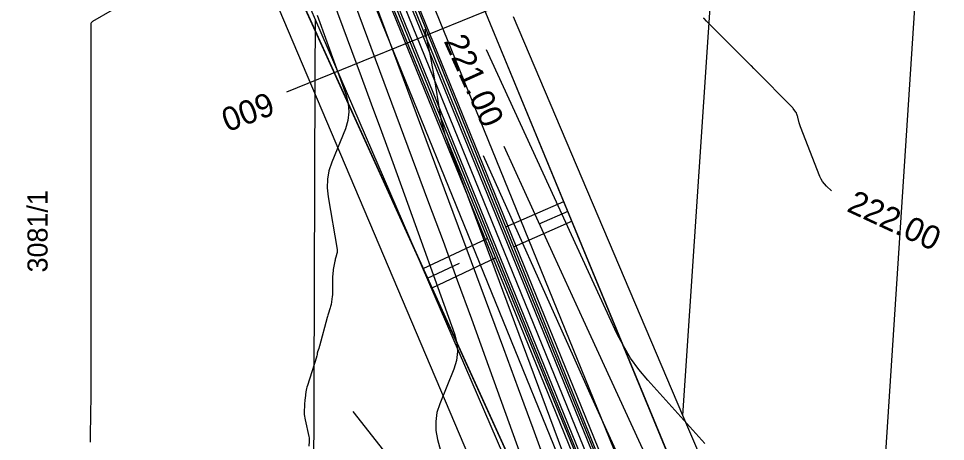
# Model space of a CAD drawing. Extents: x -534410 to -534262, y -1190162 to -1189584.
# Drawn here: x -534354.45 to -534315.26, y -1189992.54 to -1189974.68 of the extents above; entities that cross this region are included whole.
import ezdxf

# ---------------------------------------------------------------- set-up
doc = ezdxf.new("R2010")
doc.units = 0
for name, color, linetype in [('30', 7, 'Continuous'), ('31', 7, 'Continuous'), ('40', 7, 'Continuous'), ('_linie', 7, 'Continuous'), ('_N_osa', 7, 'Continuous'), ('_N_tenká', 7, 'Continuous'), ('_N_tenká_velmi', 7, 'Continuous'), ('_N_text', 7, 'Continuous'), ('_přístup', 7, 'Continuous'), ('_tenka', 7, 'Continuous'), ('_velmi_tenka', 7, 'Continuous'), ('Default', 7, 'Continuous'), ('Hranice parcel', 7, 'Continuous'), ('Parcelní čísla', 7, 'Continuous'), ('Vrstva 12', 7, 'Continuous')]:
    doc.layers.add(name, color=color, linetype=linetype)

msp = doc.modelspace()

# ---------------------------------------------------------------- linework, layer by layer
at = {"layer": '30'}
for points in [[(-534332.074, -1189993.689), (-534332.691, -1189991.999), (-534333.312, -1189990.311), (-534333.937, -1189988.624), (-534345.745, -1189956.862)], [(-534346.256, -1189960.213), (-534339.969, -1189977.123), (-534339.54, -1189978.283), (-534339.113, -1189979.443), (-534338.689, -1189980.605), (-534338.267, -1189981.768), (-534336.016, -1189988), (-534335.917, -1189988.373), (-534335.889, -1189988.744), (-534335.932, -1189989.113), (-534336.046, -1189989.482), (-534336.644, -1189990.952), (-534336.762, -1189991.321), (-534336.816, -1189991.694), (-534336.807, -1189992.071), (-534336.734, -1189992.452), (-534335.832, -1189995.749)], [(-534350.497, -1189974.321), (-534351.326, -1189974.802), (-534351.359, -1189974.826), (-534351.382, -1189974.855), (-534351.396, -1189974.89), (-534351.4, -1189974.93), (-534351.401, -1189975.144), (-534351.401, -1189975.273), (-534351.401, -1189976.416), (-534351.401, -1189976.545), (-534351.4, -1189976.759), (-534351.4, -1189976.845), (-534351.4, -1189976.93), (-534351.401, -1189977.144), (-534351.401, -1189977.273), (-534351.401, -1189978.416), (-534351.401, -1189978.545), (-534351.4, -1189978.759), (-534351.4, -1189978.845), (-534351.4, -1189978.93), (-534351.401, -1189979.144), (-534351.401, -1189979.273), (-534351.401, -1189980.416), (-534351.401, -1189980.545), (-534351.4, -1189980.759), (-534351.4, -1189980.845), (-534351.4, -1189980.93), (-534351.401, -1189981.144), (-534351.401, -1189981.273), (-534351.401, -1189982.416), (-534351.401, -1189982.545), (-534351.4, -1189982.759), (-534351.4, -1189982.845), (-534351.4, -1189982.93), (-534351.401, -1189983.144), (-534351.401, -1189983.273), (-534351.401, -1189984.416), (-534351.401, -1189984.545), (-534351.4, -1189984.759), (-534351.4, -1189984.845), (-534351.4, -1189984.93), (-534351.401, -1189985.144), (-534351.401, -1189985.273), (-534351.401, -1189986.416), (-534351.401, -1189986.545), (-534351.4, -1189986.759), (-534351.4, -1189986.845), (-534351.4, -1189986.93), (-534351.401, -1189987.144), (-534351.401, -1189987.273), (-534351.401, -1189988.416), (-534351.401, -1189988.545), (-534351.4, -1189988.759), (-534351.4, -1189988.845), (-534351.4, -1189988.93), (-534351.401, -1189989.144), (-534351.401, -1189989.273), (-534351.401, -1189990.416), (-534351.401, -1189990.545), (-534351.4, -1189990.762), (-534351.401, -1189990.803), (-534351.401, -1189990.844), (-534351.402, -1189990.886), (-534351.404, -1189990.927), (-534351.411, -1189991.091), (-534351.412, -1189991.132), (-534351.413, -1189991.174), (-534351.414, -1189991.215), (-534351.415, -1189991.256), (-534351.424, -1189992.446), (-534351.424, -1189992.486), (-534351.425, -1189992.526), (-534351.426, -1189992.566)], [(-534320.077, -1189981.949), (-534320.294, -1189981.749), (-534320.38, -1189981.66), (-534320.454, -1189981.563), (-534320.517, -1189981.458), (-534320.569, -1189981.346), (-534321.392, -1189979.243), (-534321.406, -1189979.204), (-534321.419, -1189979.165), (-534321.431, -1189979.125), (-534321.442, -1189979.085), (-534321.491, -1189978.891), (-534321.497, -1189978.868), (-534321.504, -1189978.845), (-534321.51, -1189978.822), (-534321.517, -1189978.799), (-534321.546, -1189978.707), (-534321.554, -1189978.685), (-534321.564, -1189978.663), (-534321.575, -1189978.643), (-534321.588, -1189978.623), (-534321.697, -1189978.473), (-534321.721, -1189978.442), (-534321.745, -1189978.412), (-534321.771, -1189978.383), (-534321.798, -1189978.355), (-534323.254, -1189976.899), (-534323.281, -1189976.872), (-534323.308, -1189976.844), (-534323.335, -1189976.817), (-534323.362, -1189976.789), (-534323.469, -1189976.679), (-534323.496, -1189976.652), (-534323.523, -1189976.624), (-534323.55, -1189976.597), (-534323.578, -1189976.571), (-534323.688, -1189976.463), (-534323.715, -1189976.436), (-534323.743, -1189976.41), (-534323.77, -1189976.382), (-534323.797, -1189976.355), (-534325.254, -1189974.899), (-534325.281, -1189974.872), (-534325.308, -1189974.844), (-534325.335, -1189974.817), (-534325.362, -1189974.789), (-534325.469, -1189974.679), (-534325.496, -1189974.652)], [(-534333.934, -1189980.069), (-534333.065, -1189981.984), (-534331.827, -1189984.695), (-534330.583, -1189987.403), (-534324.037, -1190001.603)]]:
    msp.add_lwpolyline(points, dxfattribs=at)
at = {"layer": '31'}
for points in [[(-534346.466, -1189957.285), (-534337.113, -1189982.443), (-534336.506, -1189984.081), (-534335.903, -1189985.722), (-534335.304, -1189987.363), (-534334.708, -1189989.006), (-534331.253, -1189998.572)], [(-534341.826, -1189974.529), (-534340.607, -1189977.906), (-534340.511, -1189978.264), (-534340.484, -1189978.621), (-534340.525, -1189978.977), (-534340.635, -1189979.331), (-534341.211, -1189980.746), (-534341.328, -1189981.103), (-534341.394, -1189981.465), (-534341.407, -1189981.832), (-534341.368, -1189982.206), (-534340.983, -1189984.424), (-534340.978, -1189984.466), (-534340.977, -1189984.509), (-534340.982, -1189984.551), (-534340.991, -1189984.593), (-534341.037, -1189984.761), (-534341.048, -1189984.803), (-534341.059, -1189984.845), (-534341.068, -1189984.887), (-534341.077, -1189984.93), (-534341.145, -1189985.272), (-534341.157, -1189985.343), (-534341.166, -1189985.415), (-534341.171, -1189985.487), (-534341.173, -1189985.56), (-534341.173, -1189986.131), (-534341.174, -1189986.203), (-534341.178, -1189986.274), (-534341.185, -1189986.346), (-534341.193, -1189986.417), (-534341.241, -1189986.749), (-534341.248, -1189986.796), (-534341.258, -1189986.843), (-534341.271, -1189986.89), (-534341.285, -1189986.936), (-534341.346, -1189987.119), (-534341.361, -1189987.165), (-534341.376, -1189987.211), (-534341.389, -1189987.257), (-534341.402, -1189987.304), (-534341.729, -1189988.516), (-534341.736, -1189988.542), (-534341.744, -1189988.568), (-534341.753, -1189988.593), (-534341.762, -1189988.619), (-534341.811, -1189988.753), (-534341.814, -1189988.762), (-534341.816, -1189988.771), (-534341.818, -1189988.78), (-534341.82, -1189988.789), (-534341.826, -1189988.826), (-534341.829, -1189988.844), (-534341.832, -1189988.863), (-534341.844, -1189988.924), (-534341.846, -1189988.937), (-534341.85, -1189988.95), (-534341.853, -1189988.963), (-534341.857, -1189988.976), (-534342.241, -1189990.175), (-534342.261, -1189990.24), (-534342.277, -1189990.306), (-534342.291, -1189990.373), (-534342.302, -1189990.44), (-534342.339, -1189990.71), (-534342.347, -1189990.777), (-534342.354, -1189990.845), (-534342.358, -1189990.913), (-534342.361, -1189990.981), (-534342.371, -1189991.319), (-534342.371, -1189991.398), (-534342.365, -1189991.476), (-534342.355, -1189991.554), (-534342.34, -1189991.631), (-534342.181, -1189992.329), (-534342.171, -1189992.38), (-534342.165, -1189992.431), (-534342.162, -1189992.482), (-534342.163, -1189992.534), (-534342.173, -1189992.741)], [(-534330.139, -1189996.477), (-534336.286, -1189979.943), (-534336.394, -1189979.631), (-534336.486, -1189979.315), (-534336.563, -1189978.994), (-534336.624, -1189978.67), (-534336.869, -1189977.175), (-534336.908, -1189976.943), (-534336.95, -1189976.711), (-534336.994, -1189976.479), (-534337.042, -1189976.248), (-534337.235, -1189975.325), (-534337.265, -1189975.15), (-534337.262, -1189975.118)], [(-534325.433, -1189992.626), (-534327.845, -1189989.955), (-534328.228, -1189989.497), (-534328.573, -1189989.014), (-534328.881, -1189988.507), (-534329.151, -1189987.974), (-534334.672, -1189975.998)], [(-534334.815, -1189980.466), (-534330.995, -1189988.966), (-534330.298, -1189990.512), (-534329.597, -1189992.056), (-534328.893, -1189993.598), (-534328.185, -1189995.139), (-534325.187, -1190001.643), (-534324.603, -1190003.024), (-534324.113, -1190004.435), (-534323.717, -1190005.875), (-534323.414, -1190007.344), (-534322.095, -1190014.986), (-534321.984, -1190015.614), (-534321.868, -1190016.242), (-534321.747, -1190016.868), (-534321.621, -1190017.494), (-534321.51, -1190018.033)]]:
    msp.add_lwpolyline(points, dxfattribs=at)
at = {"layer": '_linie'}
for points in [[(-534351.8, -1189951.99), (-534346.88, -1189964.25), (-534328.11, -1190005.55), (-534325.796, -1190021.686), (-534325.86, -1190050.97), (-534326.22, -1190078.56), (-534326.79, -1190120.4), (-534329.12, -1190134.93), (-534323.49, -1190133.89), (-534321.38, -1190121.46), (-534319.59, -1190053.22), (-534320.45, -1190021.195), (-534322.75, -1190003.33), (-534340.65, -1189960.04), (-534344.52, -1189948.89)], [(-534347.45, -1189950.137), (-534345.54, -1189954.54), (-534325.02, -1190005.35), (-534322.054, -1190021.393), (-534321.72, -1190051.56), (-534322.31, -1190078.15), (-534323.81, -1190120.37), (-534326.521, -1190134.45)], [(-534328.194, -1190134.759), (-534324.85, -1190120.45), (-534324.6, -1190078.17), (-534323.54, -1190051.92), (-534323.273, -1190021.516), (-534325.81, -1190005.43), (-534346.66, -1189954.59), (-534348.342, -1189950.518)]]:
    msp.add_lwpolyline(points, dxfattribs=at)
at = {"layer": '_N_osa'}
msp.add_lwpolyline([(-534327.357, -1190134.604), (-534324.33, -1190120.41), (-534323.455, -1190078.16), (-534322.63, -1190051.74), (-534322.663, -1190021.455), (-534325.415, -1190005.39), (-534346.1, -1189954.565), (-534347.892, -1189950.326)], dxfattribs=at)
at = {"layer": '_N_tenká'}
for points in [[(-534326.133, -1190134.378), (-534323.183, -1190120.543), (-534322.305, -1190078.19), (-534321.48, -1190051.757), (-534321.513, -1190021.356), (-534324.303, -1190005.072), (-534345.038, -1189954.124), (-534346.832, -1189949.878)], [(-534327.623, -1190134.654), (-534324.579, -1190120.381), (-534323.705, -1190078.154), (-534322.88, -1190051.736), (-534322.913, -1190021.476), (-534325.657, -1190005.459), (-534346.331, -1189954.661), (-534348.122, -1189950.423)], [(-534327.091, -1190134.555), (-534324.081, -1190120.439), (-534323.205, -1190078.166), (-534322.38, -1190051.744), (-534322.413, -1190021.433), (-534325.173, -1190005.321), (-534345.869, -1189954.469), (-534347.661, -1189950.228)], [(-534328.581, -1190134.83), (-534325.477, -1190120.277), (-534324.605, -1190078.13), (-534323.78, -1190051.723), (-534323.813, -1190021.553), (-534326.527, -1190005.708), (-534347.162, -1189955.006), (-534348.951, -1189950.773)]]:
    msp.add_lwpolyline(points, dxfattribs=at)
at = {"layer": '_N_tenká_velmi'}
for points in [[(-534326.772, -1190134.496), (-534323.781, -1190120.474), (-534322.905, -1190078.174), (-534322.08, -1190051.748), (-534322.113, -1190021.407), (-534324.883, -1190005.238), (-534345.592, -1189954.354), (-534347.385, -1189950.112)], [(-534327.943, -1190134.713), (-534324.879, -1190120.346), (-534324.005, -1190078.146), (-534323.18, -1190051.732), (-534323.213, -1190021.502), (-534325.947, -1190005.542), (-534346.608, -1189954.776), (-534348.398, -1189950.54)], [(-534327.73, -1190134.673), (-534324.679, -1190120.37), (-534323.805, -1190078.151), (-534322.98, -1190051.735), (-534323.013, -1190021.485), (-534325.754, -1190005.487), (-534346.423, -1189954.699), (-534348.214, -1189950.462)], [(-534326.985, -1190134.536), (-534323.981, -1190120.45), (-534323.105, -1190078.169), (-534322.28, -1190051.745), (-534322.313, -1190021.425), (-534325.076, -1190005.293), (-534345.777, -1189954.431), (-534347.569, -1189950.189)]]:
    msp.add_lwpolyline(points, dxfattribs=at)
at = {"layer": '_N_text'}
msp.add_lwpolyline([(-534332.014, -1189973.259), (-534343.129, -1189977.783)], dxfattribs=at)
at = {"layer": '_přístup'}
msp.add_lwpolyline([(-534330.552, -1190135.191), (-534328.648, -1190119.819), (-534326.845, -1190024.247), (-534332.805, -1189999.297), (-534354.454, -1189948.317)], dxfattribs=at)
at = {"layer": '_tenka'}
for points in [[(-534351.8, -1189951.99), (-534346.88, -1189964.25), (-534328.11, -1190005.55), (-534325.796, -1190021.686), (-534325.86, -1190050.97), (-534326.22, -1190078.56), (-534326.79, -1190120.4), (-534329.12, -1190134.93), (-534323.49, -1190133.89), (-534321.38, -1190121.46), (-534319.59, -1190053.22), (-534320.45, -1190021.195), (-534322.75, -1190003.33), (-534340.65, -1189960.04), (-534344.52, -1189948.89)], [(-534327.55, -1190134.64), (-534323.49, -1190133.89), (-534321.38, -1190121.46), (-534319.59, -1190053.22), (-534320.45, -1190021.195), (-534322.75, -1190003.33), (-534340.65, -1189960.04), (-534344.52, -1189948.89)], [(-534347.45, -1189950.137), (-534345.54, -1189954.54), (-534325.02, -1190005.35), (-534322.054, -1190021.393), (-534321.72, -1190051.56), (-534322.31, -1190078.15), (-534323.81, -1190120.37), (-534326.521, -1190134.45)], [(-534347.45, -1189950.137), (-534345.54, -1189954.54), (-534325.02, -1190005.35), (-534322.054, -1190021.393), (-534321.72, -1190051.56), (-534322.31, -1190078.15), (-534323.81, -1190120.37), (-534326.521, -1190134.45)], [(-534328.194, -1190134.759), (-534324.85, -1190120.45), (-534324.6, -1190078.17), (-534323.54, -1190051.92), (-534323.273, -1190021.516), (-534325.81, -1190005.43), (-534346.66, -1189954.59), (-534348.342, -1189950.518)], [(-534328.194, -1190134.759), (-534324.85, -1190120.45), (-534324.6, -1190078.17), (-534323.54, -1190051.92), (-534323.273, -1190021.516), (-534325.81, -1190005.43), (-534346.66, -1189954.59), (-534348.342, -1189950.518)], [(-534351.8, -1189951.99), (-534346.88, -1189964.25), (-534328.11, -1190005.55), (-534325.796, -1190021.686), (-534325.86, -1190050.97), (-534326.22, -1190078.56), (-534326.79, -1190120.4), (-534329.12, -1190134.93), (-534327.55, -1190134.64)]]:
    msp.add_lwpolyline(points, dxfattribs=at)
at = {"layer": '_velmi_tenka'}
for p, q in [((-534331.411, -1189982.412), (-534333.862, -1189983.493)), ((-534331.229, -1189982.823), (-534332.455, -1189983.364)), ((-534331.048, -1189983.235), (-534333.499, -1189984.317)), ((-534337.349, -1189985.235), (-534334.64, -1189983.959)), ((-534337.158, -1189985.642), (-534335.803, -1189985.004)), ((-534336.966, -1189986.049), (-534334.257, -1189984.773))]:
    msp.add_line(p, q, dxfattribs=at)
at = {"layer": 'Default'}
for p, q in [((-534322.75, -1190003.33), (-534340.65, -1189960.04)), ((-534346.88, -1189964.25), (-534328.11, -1190005.55))]:
    msp.add_line(p, q, dxfattribs=at)
at = {"layer": 'Hranice parcel'}
for p, q in [((-534326.36, -1189991.44), (-534323.33, -1189946.13)), ((-534319.25, -1190015.38), (-534314.72, -1189945.99)), ((-534351.04, -1189953.66), (-534341.9, -1189974.75)), ((-534341.9, -1189974.75), (-534333.99, -1189993.03)), ((-534326.36, -1189991.44), (-534333.52, -1189974.6))]:
    msp.add_line(p, q, dxfattribs=at)
for points in [[(-534341.99, -1190003.45), (-534341.91, -1189977.12), (-534341.9, -1189974.75)], [(-534319.25, -1190015.38), (-534319.67, -1190011.96), (-534324.68, -1189995.39), (-534326.36, -1189991.44)]]:
    msp.add_lwpolyline(points, dxfattribs=at)
at = {"layer": 'Vrstva 12'}
msp.add_lwpolyline([(-534315.834, -1190022.126), (-534329.125, -1190005.478), (-534340.302, -1189991.272)], dxfattribs=at)

# ---------------------------------------------------------------- texts
at = {"layer": '40'}
for s, rotation, p in [('221.00', 294.2628, (-534336.486, -1189975.623)), ('222.00', 335.1944, (-534319.479, -1189982.794))]:
    msp.add_text(s, height=1, rotation=rotation, dxfattribs=at).set_placement(p)
at = {"layer": '_N_text'}
msp.add_text('600', height=1, rotation=200.9191, dxfattribs=at).set_placement((-534343.893, -1189977.75))
at = {"layer": 'Parcelní čísla'}
msp.add_text('3081/1', height=0.85, rotation=90, dxfattribs=at).set_placement((-534353.226, -1189985.4))

doc.saveas('drawing.dxf')
